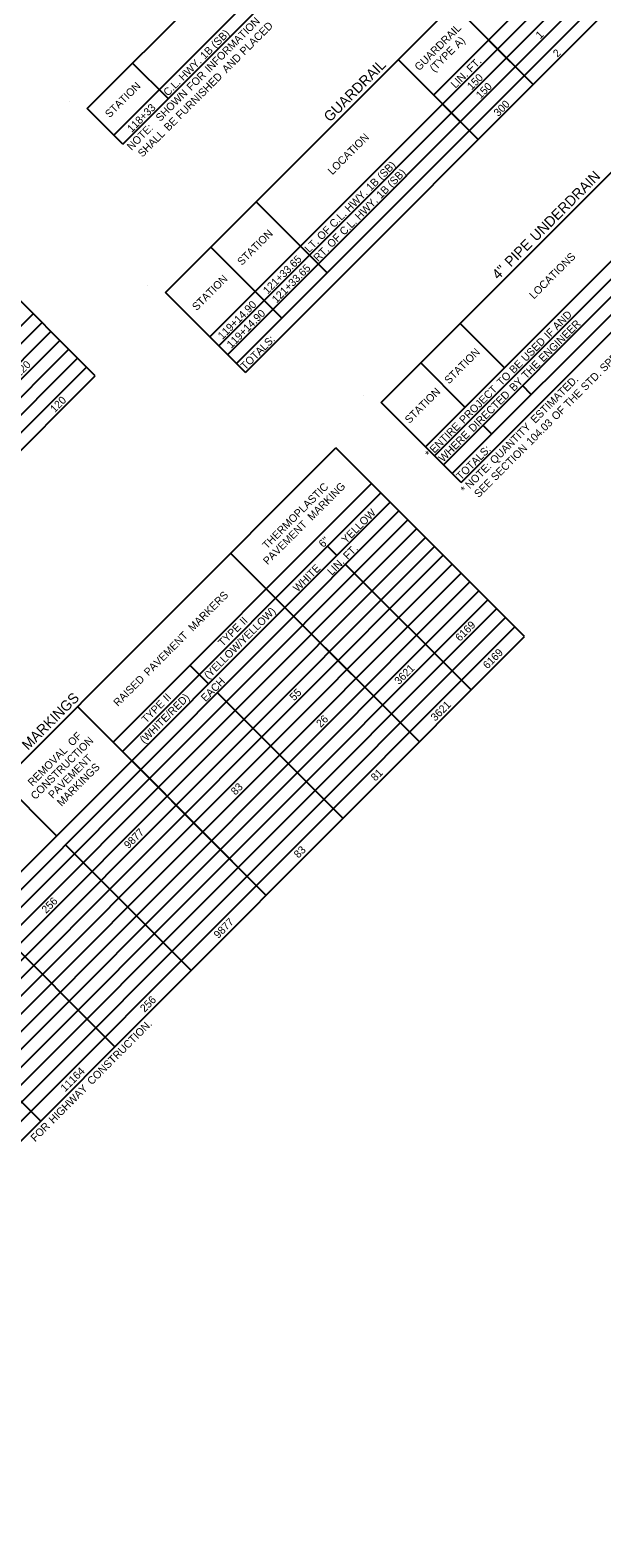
# Model space of a CAD drawing. Extents: x 1675667 to 1681231, y 227227 to 232694.
# Drawn here: x 1676544 to 1676988, y 227232 to 228402 of the extents above; entities that cross this region are included whole.
import ezdxf

# ---------------------------------------------------------------- set-up
doc = ezdxf.new("R2010")
doc.units = 0
doc.layers.add('Default', color=7, linetype='Continuous')
doc.layers.add('R_Annotation', color=7, linetype='Continuous')

msp = doc.modelspace()

# ---------------------------------------------------------------- linework, layer by layer
at = {"layer": 'Default'}
for p, q in [((1676588.4, 228340.8), (1676783.5, 228535.9)), ((1676609.1, 228320.1), (1676804.2, 228515.2)), ((1676616, 228313.2), (1676811.1, 228508.3)), ((1676649.1, 228198), (1676957.9, 228506.9)), ((1676857.3, 228351.1), (1676985.5, 228479.4)), ((1676683.6, 228163.6), (1676992.4, 228472.5)), ((1676690.5, 228156.7), (1676999.3, 228465.6)), ((1676697.4, 228149.8), (1677006.2, 228458.7)), ((1676704.3, 228142.9), (1677013.1, 228451.8)), ((1676711.2, 228136), (1677020, 228444.9)), ((1676934.5, 228359.4), (1676872.4, 228421.4)), ((1676594.6, 228133.3), (1676318.8, 228409)), ((1676594.6, 228133.3), (1676318.8, 228409)), ((1676934.5, 228359.4), (1676900, 228393.9)), ((1676816.6, 228112.7), (1677084.4, 228380.5)), ((1676651.2, 228348.4), (1676623.6, 228376)), ((1676891.8, 228316.6), (1676829.7, 228378.7)), ((1676851.1, 228078.2), (1677118.9, 228346.1)), ((1676616, 228313.2), (1676588.4, 228340.8)), ((1676616, 228313.2), (1676588.4, 228340.8)), ((1676858, 228071.3), (1677125.8, 228339.2)), ((1676891.8, 228316.6), (1676864.2, 228344.2)), ((1676864.9, 228064.4), (1677132.7, 228332.3)), ((1676871.8, 228057.5), (1677139.6, 228325.4)), ((1676878.7, 228050.6), (1677146.5, 228318.5)), ((1676851.1, 228078.2), (1677071.7, 228298.9)), ((1676774.6, 228213.2), (1676719.4, 228268.4)), ((1676739.4, 228178), (1676684.3, 228233.2)), ((1676774.6, 228213.2), (1676753.9, 228233.9)), ((1676635.3, 228203.5), (1676635.3, 228203.5)), ((1676711.2, 228136), (1676649.1, 228198)), ((1676711.2, 228136), (1676649.1, 228198)), ((1676739.4, 228178), (1676718.7, 228198.7)), ((1675911.8, 227546.8), (1676546.3, 228181.5)), ((1675918.7, 227539.9), (1676553.2, 228174.6)), ((1676912.4, 228139.6), (1676878, 228174)), ((1675925.6, 227533), (1676560.1, 228167.7)), ((1675932.5, 227526.1), (1676567, 228160.8)), ((1675939.4, 227519.2), (1676573.9, 228153.9)), ((1675946.3, 227512.3), (1676580.8, 228147)), ((1675953.2, 227505.4), (1676587.7, 228140.1)), ((1676881.8, 228108.9), (1676847.3, 228143.4)), ((1675960.1, 227498.6), (1676594.6, 228133.3)), ((1676933.1, 228118.9), (1676926.2, 228125.8)), ((1676933.1, 228118.9), (1676926.2, 228125.8)), ((1676802.8, 228118.2), (1676802.8, 228118.2)), ((1676878.7, 228050.6), (1676816.6, 228112.7)), ((1676878.7, 228050.6), (1676816.6, 228112.7)), ((1676902.4, 228088.2), (1676895.5, 228095.1)), ((1676902.4, 228088.2), (1676895.5, 228095.1)), ((1676082.4, 227378.3), (1676781.4, 228077.5)), ((1676927.9, 227931), (1676781.4, 228077.5)), ((1676608.4, 227849.2), (1676809, 228049.9)), ((1676615.6, 227842), (1676816.2, 228042.7)), ((1676131.4, 227329.4), (1676830.4, 228028.5)), ((1676328.9, 227540.7), (1676823.5, 228035.4)), ((1676138.3, 227322.5), (1676837.3, 228021.6)), ((1676145.2, 227315.6), (1676844.1, 228014.7)), ((1676152, 227308.7), (1676851, 228007.8)), ((1676158.9, 227301.8), (1676857.9, 228000.9)), ((1676165.8, 227294.9), (1676864.8, 227994.1)), ((1676846.2, 227849.3), (1676699.7, 227995.8)), ((1676782.1, 227994), (1676774.9, 228001.3)), ((1676172.7, 227288), (1676871.7, 227987.2)), ((1676886.6, 227889.6), (1676789, 227987.1)), ((1676886.6, 227889.6), (1676789, 227987.1)), ((1676179.6, 227281.1), (1676878.6, 227980.3)), ((1676186.5, 227274.2), (1676885.5, 227973.4)), ((1676193.4, 227267.3), (1676892.4, 227966.5)), ((1676200.3, 227260.4), (1676899.3, 227959.6)), ((1676207.2, 227253.5), (1676906.2, 227952.7)), ((1676846.2, 227849.3), (1676741.8, 227953.7)), ((1676214.1, 227246.6), (1676913.1, 227945.8)), ((1676221.3, 227239.4), (1676920.3, 227938.6)), ((1676228.9, 227231.8), (1676927.9, 227931)), ((1676682.5, 227894.4), (1676668, 227908.9)), ((1676727.3, 227730.3), (1676580.8, 227876.8)), ((1676787, 227790), (1676689.4, 227887.5)), ((1676787, 227790), (1676689.4, 227887.5)), ((1676727.3, 227730.3), (1676622.9, 227834.8)), ((1676564.6, 227776.5), (1676522.6, 227818.6)), ((1676669.1, 227672.1), (1676571.5, 227769.6)), ((1676669.1, 227672.1), (1676571.5, 227769.6)), ((1676609.8, 227612.8), (1676512.2, 227710.3)), ((1676609.8, 227612.8), (1676512.2, 227710.3)), ((1676552.2, 227555.2), (1676454.7, 227652.7)), ((1676552.2, 227555.2), (1676454.7, 227652.7))]:
    msp.add_line(p, q, dxfattribs=at)
at = {"layer": 'R_Annotation'}
msp.add_line((1676574.6, 228346.3), (1676574.6, 228346.3), dxfattribs=at)

# ---------------------------------------------------------------- texts
at = {"layer": 'Default'}
for s, height, p in [(' INFORMATION', 6, (1676681.6, 228366.7)), (' PLACED', 6, (1676708.8, 228380.2)), ('GUARDRAIL', 6, (1676846.1, 228369.6)), (' (SB)', 6, (1676686.5, 228385.5)), (' A)', 6, (1676875, 228385.7)), ('1', 6, (1676940.1, 228394.3)), (' 1B', 6, (1676678, 228376.9)), (' AND', 6, (1676695, 228366.3)), ('(TYPE', 6, (1676857.8, 228368.6)), (' FT.', 6, (1676885, 228366.8)), ('2', 6, (1676953.5, 228380.1)), (' FURNISHED', 6, (1676659.1, 228330.4)), (' HWY.', 6, (1676661.4, 228360.3)), (' FOR', 6, (1676667.5, 228352.6)), ('GUARDRAIL', 8, (1676776.8, 228329.8)), ('LIN.', 6, (1676874.2, 228356)), ('STATION', 6, (1676605.7, 228333.1)), ('C.L.', 6, (1676651, 228349.9)), ('150', 6, (1676886.8, 228354.7)), ('150', 6, (1676893.7, 228347.8)), ('118+33', 6, (1676622.9, 228321.8)), ('   SHOWN', 6, (1676640.3, 228325.5)), ('300', 6, (1676907.5, 228334.1)), (' BE', 6, (1676649.9, 228321.2)), ('NOTE:', 6, (1676622.7, 228307.9)), (' SHALL', 6, (1676629.6, 228301)), ('LOCATION', 6, (1676778.7, 228288.9)), (' (SB)', 6, (1676815.5, 228283.4)), (' 1B', 6, (1676806.9, 228274.8)), (' (SB)', 6, (1676823.3, 228277.5)), (' UNDERDRAIN', 8, (1676934.9, 228235)), (' HWY.', 6, (1676790.3, 228258.2)), (' 1B', 6, (1676814.8, 228268.9)), (' HWY.', 6, (1676798.2, 228252.3)), (' C.L.', 6, (1676778.3, 228246.2)), (' C.L.', 6, (1676786.2, 228240.3)), ('STATION', 6, (1676708.4, 228218.6)), ('LT.', 6, (1676760.6, 228228.5)), (' OF', 6, (1676768.7, 228236.6)), (' OF', 6, (1676776.5, 228230.7)), (' PIPE', 8, (1676915.1, 228215.2)), ('RT.', 6, (1676767.5, 228221.6)), ('LOCATIONS', 6, (1676935.2, 228192.5)), ('121+33.65', 6, (1676728.4, 228196.3)), ('121+33.65', 6, (1676735.3, 228189.4)), ('4"', 8, (1676907.4, 228207.5)), ('STATION', 6, (1676673.3, 228183.5)), ('119+14.90', 6, (1676693.3, 228161.1)), ('119+14.90', 6, (1676700.2, 228154.3)), (' AND', 6, (1676951.7, 228166.8)), (' ENGINEER', 6, (1676940.8, 228142)), (' IF', 6, (1676945.1, 228160.1)), ('TOTALS:', 6, (1676711, 228137.5)), (' USED', 6, (1676927.3, 228142.3)), (' SPECS.', 6, (1676988.3, 228134.4)), ('STATION', 6, (1676869.2, 228126.6)), (' BE', 6, (1676918, 228133.1)), (' THE', 6, (1676927.6, 228128.9)), ('120', 6, (1676535.6, 228132)), (' TO', 6, (1676908.4, 228123.5)), (' STD.', 6, (1676973.6, 228119.7)), ('STATION', 6, (1676838.5, 228095.9)), (' PROJECT', 6, (1676879.2, 228094.3)), (' BY', 6, (1676918.1, 228119.3)), (' ESTIMATED.', 6, (1676934.6, 228094.5)), (' THE', 6, (1676960.4, 228106.6)), ('120', 6, (1676563.1, 228104.4)), (' DIRECTED', 6, (1676886.5, 228087.7)), (' OF', 6, (1676950.8, 228096.9)), (' 104.03', 6, (1676931.3, 228077.4)), ('ENTIRE', 6, (1676857.8, 228072.9)), ('WHERE', 6, (1676864.7, 228066)), (' QUANTITY', 6, (1676903, 228062.9)), ('TOTALS:', 6, (1676878.5, 228052.2)), (' SECTION', 6, (1676903.8, 228049.9)), ('*', 6, (1676854.3, 228069.4)), ('NOTE:', 6, (1676885.4, 228045.3)), ('SEE', 6, (1676892.3, 228038.4)), ('THERMOPLASTIC', 6, (1676727.9, 227998.5)), (' MARKING', 6, (1676761.3, 228019.1)), ('*', 6, (1676881.9, 228041.8)), ('YELLOW', 6, (1676789.3, 228002.9)), ('PAVEMENT', 6, (1676728.4, 227986.3)), ('6"', 6, (1676771.6, 227999.7)), (' FT.', 6, (1676789, 227988.8)), ('WHITE', 6, (1676751.7, 227965.3)), ('LIN.', 6, (1676778.2, 227978.1)), (' MARKERS', 6, (1676668.8, 227933)), ('(YELLOW/YELLOW)', 6, (1676682.6, 227897.6)), (' II', 6, (1676708.7, 227938.1)), (' PAVEMENT', 6, (1676634.3, 227898.5)), ('TYPE', 6, (1676693.5, 227922.9)), ('6169', 6, (1676877.7, 227926.9)), ('6169', 6, (1676899.1, 227905.5)), ('RAISED', 6, (1676612.2, 227876.4)), ('3621', 6, (1676830.4, 227893.3)), ('EACH', 6, (1676680.2, 227880)), ('55', 6, (1676749, 227880.8)), (' MARKINGS', 8, (1676540.3, 227840.3)), ('(WHITE/RED)', 6, (1676632.7, 227847.6)), ('TYPE', 6, (1676634.1, 227863.4)), (' II', 6, (1676649.3, 227878.6)), ('3621', 6, (1676858.6, 227865)), ('26', 6, (1676769.7, 227860.2)), ('CONSTRUCTION', 6, (1676548, 227804.1)), (' OF', 6, (1676575.2, 227844)), ('REMOVAL', 6, (1676545.7, 227814.5)), ('PAVEMENT', 6, (1676561.6, 227804.9)), ('MARKINGS', 6, (1676568.4, 227799)), ('81', 6, (1676812.1, 227818.5)), ('83', 6, (1676703.4, 227807.6)), ('9877', 6, (1676620.4, 227766)), ('83', 6, (1676752.3, 227758.7)), ('256', 6, (1676556.4, 227715.8)), ('9877', 6, (1676690.1, 227696.4)), ('256', 6, (1676632.9, 227639.2)), (' CONSTRUCTION.', 6, (1676590.3, 227581.2)), ('11164', 6, (1676571.2, 227577.5)), (' HIGHWAY', 6, (1676560.4, 227551.2)), (' FOR', 6, (1676546.3, 227537.1))]:
    msp.add_text(s, height=height, rotation=45.007, dxfattribs=at).set_placement(p)

doc.saveas('drawing.dxf')
